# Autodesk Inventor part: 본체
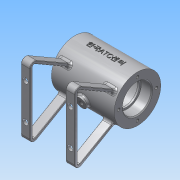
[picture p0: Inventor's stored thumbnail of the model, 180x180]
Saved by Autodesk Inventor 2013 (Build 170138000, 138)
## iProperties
Created: 2016-03
Part Number: 본체
Material: 알루미늄 6061
Document SubType Name: Modeling
Designer: Administrator
Density: 2.71 g/cm^3
Mass: 213.146 g
Surface Area: 333.938 cm^2
Volume: 78.6516 cm^3
Author: Administrator
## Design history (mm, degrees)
sketch "스케치1"
  geometry: L1 (0, 21)-(21, 21); L2 (21, 21)-(21, 14); L3 (21, 14)-(23, 14); L4 (23, 14)-(23, 16); L5 (23, 16)-(35, 16); L6 (35, 16)-(35, 26); L7 (35, 26)-(0, 26); L8 (0, 26)-(0, 21); L9 (0, 0)-(35, 0)
  constraints: 18 end point, 5 parallel, 3 perpendicular, 1 horizontal, 1 point on line
  dimensions: "d0" = 35 distance of L9.start L9.end; "d2" = 12 distance of L4.end L5.end; "d3" = 2 distance of L2.end L3.end; "d4" = 21 distance of L1.start L1.end; "d6" = 32 diameter of L5 L9; "d7" = 28 diameter of L3 L9; "d8" = 42 diameter of L1 L9; "d9" = 52 diameter of L7 L9
revolve "회전1" sketch "스케치1" stored, may be unused: angle "d10" = 90 deg
sketch "스케치2"
  geometry: C1 r 16 at (0, 0) reference; 1 further point
  constraints: 1 vertical alignment
  dimensions: "d11" = 21 distance of C1.centre point (0, 21)
hole "구멍1" sketch "스케치2" at (0, 21) diameter "d12" = 3.242; stored, may be unused: countersink angle "d16" = 90 deg, drill point angle "d18" = 118 deg; dims "d13" = 8, "d14" = 4, "d15" = 2, "d17" = 10
node "작업 평면1"
sketch "스케치3"
  geometry: L1 (-20, 16.613)-(-57.5, 38.264); L2 (-65, 33.934)-(-65, -33.934); L3 (-57.5, -38.264)-(-20, -16.613); L4 (0, 0)-(-65, 0); L5 (-21.791, 14.183)-(-59, 35.666); L6 (-62, 33.934)-(-62, -33.934); L7 (-59, -35.666)-(-21.791, -14.183); A1 r 26 centre (0, 0) between (-20, 16.613) and (-20, -16.613) reference; A2 r 5 centre (-60, 33.934) between (-57.5, 38.264) and (-65, 33.934); A3 r 5 centre (-60, -33.934) between (-65, -33.934) and (-57.5, -38.264); A4 r 2 centre (-60, 33.934) between (-59, 35.666) and (-62, 33.934); A5 r 2 centre (-60, -33.934) between (-62, -33.934) and (-59, -35.666); 2 further points
  constraints: 14 end point, 12 point on circle, 4 centre point, 4 tangent, 2 point on line, 1 equal radius, 1 horizontal, 1 midpoint, 1 vertical, 4 other
  dimensions: "d23" = 30 deg angle of L4 L3; "d24" = 30 deg angle of L1 L4; "d25" = 45 horizontal distance of point (-65, -42.594) L3.end; "d27" = 65 distance from line of L2 point (0, 0); "d29" = 5 radius of A2; "d30" = 3 distance between parallel lines of L5 L1
extrude "돌출1" join sketch "스케치3" distance "d31" = 10; taper "d32" = 0 deg
sketch "스케치4"
  geometry: L1 (0, 67.868)-(0, 0) reference; L2 (10, 67.868)-(10, 0) reference; 3 further points
  dimensions: "d33" = 20 vertical distance of point (-20, 33.934) point (5, 53.934); "d34" = 20 vertical distance of point (5, 13.934) point (-20, 33.934); "d35" = 5 distance from line of point (5, 53.934) L1; "d36" = 5 distance from line of L2 point (5, 13.934)
hole "구멍2" sketch "스케치4" at (5, 53.934), (5, 13.934) diameter "d37" = 6; stored, may be unused: countersink angle "d41" = 90 deg, drill point angle "d43" = 118 deg; dims "d38" = 8, "d39" = 4, "d40" = 2, "d42" = 6
fillet "모깎기1" dims "d44" = 0.3
fillet "모깎기2" dims "d45" = 3
chamfer "모따기1" distance "d46" = 1; stored, may be unused: second distance "d47" = 2, angle "d48" = 45 deg
fillet "모깎기3" dims "d49" = 0.5
fillet "모깎기4" dims "d50" = 3
node "작업 평면2"
sketch "스케치5"
  geometry: 2 further points
  constraints: 1 coincident, 1 other
feature "엠보싱1" sketch "스케치5" dims "d0" = 35, "d2" = 12, "d3" = 2, "d4" = 21, "d6" = 32, "d7" = 28, "d8" = 42, "d9" = 52, "d52" = 0.5, "d53" = 0
node "작업 평면3"
sketch "스케치6"
  geometry: C1 r 5 at (0, 0); 1 further point
  constraints: 1 centre point, 1 coincident
  dimensions: "d55" = 10 diameter of C1
extrude "돌출2" join sketch "스케치6" stored distance "d56" = 10; taper "d57" = 0 deg
sketch "스케치7"
  geometry: 2 further points
  constraints: 1 coincident
hole "구멍3" sketch "스케치7" at (0, 0) diameter "d58" = 5.188; stored, may be unused: countersink angle "d62" = 90 deg, drill point angle "d64" = 118 deg; dims "d59" = 8, "d60" = 4, "d61" = 2, "d63" = 6
sketch "스케치8"
  geometry: L1 (-64.5, 33.934)-(-64.5, -33.934) reference; L2 (0, 0)-(-64.5, 0); L3 (0, 0)-(-28.012, -7.506)
  constraints: 4 end point, 1 midpoint
  dimensions: "d65" = 29 distance of L2.start L3.end; "d66" = 15 deg angle of L3 L2
node "작업 평면4"
sketch "스케치9"
  geometry: C1 r 6 at (0, 0); 1 further point
  constraints: 1 centre point, 1 coincident
  dimensions: "d67" = 12 diameter of C1
extrude "돌출3" join sketch "스케치9" stored distance "d68" = 10; taper "d69" = 0 deg
sketch "스케치10"
  geometry: 2 further points
  constraints: 1 coincident
hole "구멍4" sketch "스케치10" at (0, 0) diameter "d70" = 5.188; stored, may be unused: countersink angle "d74" = 90 deg, drill point angle "d76" = 118 deg; dims "d71" = 8, "d72" = 4, "d73" = 2, "d75" = 6
fillet "모깎기5" dims "d77" = 2
node "솔리드1"
pattern_circular "원형 패턴1" dims angle "d20" = 360 deg
mirror "대칭1"
other parameters: "d51" = 45.25, "d54" = 29
